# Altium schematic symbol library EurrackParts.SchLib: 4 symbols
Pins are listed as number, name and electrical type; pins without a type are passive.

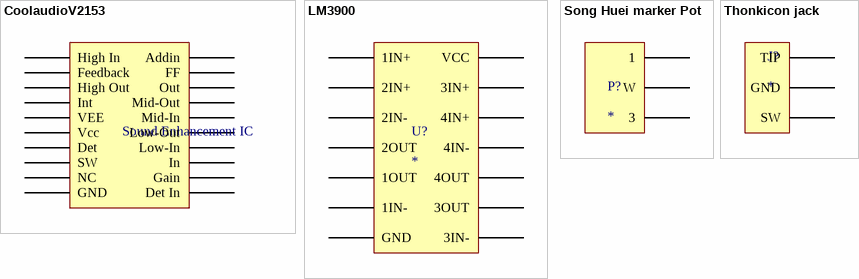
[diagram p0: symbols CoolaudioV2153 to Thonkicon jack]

## CoolaudioV2153
designator U?, comment Sound Enhancement IC
footprint SOIC20 - duplicate
pins: 1 High In, 2 Feedback, 3 High Out, 4 Int, 5 VEE, 6 Vcc, 7 Det, 8 SW, 9 NC, 10 GND, 11 Det In, 12 Gain, 13 In, 14 Low-In, 15 Low-Out, 16 Mid-In, 17 Mid-Out, 18 Out, 19 FF, 20 Addin

## LM3900
designator U?
footprint LM3900 (LM3900 SOIC)
pins: 1 1IN+, 2 2IN+, 3 2IN-, 4 2OUT, 5 1OUT, 6 1IN-, 7 GND, 8 3IN-, 9 3OUT, 10 4OUT, 11 4IN-, 12 4IN+, 13 3IN+, 14 VCC

## Song Huei marker Pot
designator P?
footprint SonGueiPot
pins: 1, 2 W, 3

## Thonkicon jack
designator J?
footprint Thonkiconn Pot PJ301M (PJ301 Thonkicon Jack from Thonk)
pins: 1 GND, 2 SW, 3 TIP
